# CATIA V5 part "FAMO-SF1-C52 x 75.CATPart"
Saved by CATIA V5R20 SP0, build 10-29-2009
Part number: FAMO-SF1-C52 x 75
Definition: NONE
Nomenclature: FAMO-SF1-C52 x 75
Source: Unknown
Description: FAMO-SF1-C52 x 75
Bounding box of the stored display mesh (mm): x -40 to 35, y -39.5 to 39.5, z -39.5 to 39.5
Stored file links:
  C:\Users\Utente\Desktop\IO LAVORO\3D X SITO CF\X SITO\FAMO\FAMO-SF1-C52 x 75.CATPart

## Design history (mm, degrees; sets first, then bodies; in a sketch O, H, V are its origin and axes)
Body1 "FAMO-SF1-C52 x 75" (main body)
  Solid1: solid without history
